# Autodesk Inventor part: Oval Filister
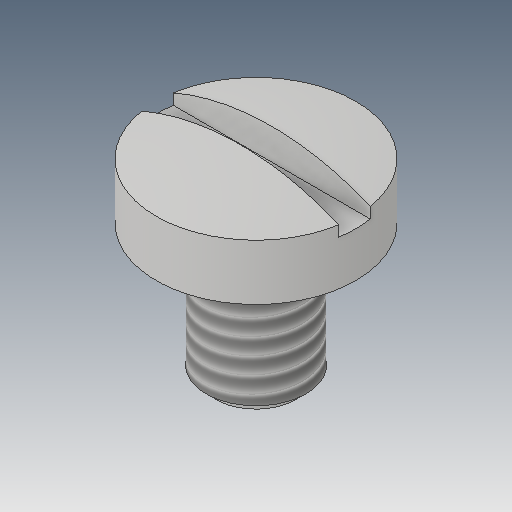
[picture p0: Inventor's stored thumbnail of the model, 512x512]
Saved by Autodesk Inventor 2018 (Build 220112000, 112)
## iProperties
Created: 2016-06
Part Number: Oval Filister
Material: Generic
Document SubType Name: Modeling
Designer: CADCIM
Density: 1 g/cm^3
Appearance: Default
Mass: 0.639925 g
Surface Area: 5.32794 cm^2
Volume: 0.639925 cm^3
Author: CADCIM
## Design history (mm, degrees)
sketch "Sketch1"
  geometry: 1 further point
sketch "Sketch2"
  geometry: C1 r 3 at (0, 0); 1 further point
  constraints: 1 centre point, 1 coincident
  dimensions: "d0" = 6 diameter of C1
extrude "Extrusion1" new body sketch "Sketch2" distance "d1" = 8; taper "d2" = 0 deg
sketch "Sketch3"
  geometry: 1 further point
sketch "Sketch4"
  geometry: L1 (8, 0)-(8, -6); L2 (8, -3)-(8, 3) reference; L3 (8, -6)-(11.35, -6); L4 (12.6, 0)-(8, 0); A1 r 15.025 centre (-2.425, 0) between (11.35, -6) and (12.6, 0); 2 further points
  constraints: 6 end point, 2 midpoint, 2 point on circle, 1 centre point, 1 horizontal, 1 horizontal alignment, 1 perpendicular, 1 point on line, 1 vertical
  dimensions: "d3" = 6 distance of L1.start L1.end; "d4" = 4.6 distance of L4.start L1.start; "d5" = 1.25 horizontal distance of L3.end L4.start
revolve "Revolution1" sketch "Sketch4" stored, may be unused: angle "d6" = 90 deg
workplane "Work Plane1"
sketch "Sketch5"
  geometry: L1 (6.611, -0.95)-(-6.611, -0.95); L2 (-6.611, -0.95)-(-6.611, 0.95); L3 (-6.611, 0.95)-(6.611, 0.95); L4 (6.611, 0.95)-(6.611, -0.95); L5 (6.611, 0)-(-6.611, 0); 2 further points
  constraints: 10 end point, 3 midpoint, 2 parallel, 1 coincident, 1 horizontal, 1 perpendicular
  dimensions: "d8" = 1.9 distance of L3.end L1.start
extrude "Extrusion2" cut sketch "Sketch5" distance "d9" = 1.9; taper "d10" = 0 deg
thread "Thread1" dims "d11" = 10, "d12" = 0
chamfer "Chamfer1" distance "d13" = 0.6; stored, may be unused: second distance "d14" = 2, angle "d15" = 45 deg
body "Solid1"
other parameters: "d7" = -4.6
